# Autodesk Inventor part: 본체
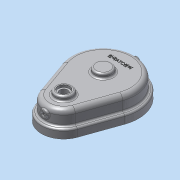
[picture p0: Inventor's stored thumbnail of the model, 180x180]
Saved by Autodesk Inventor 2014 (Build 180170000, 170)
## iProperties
Created: 2024-05
Part Number: 본체
Material: 알루미늄 6061
Document SubType Name: Modeling
Designer: dg
Density: 2.71 g/cm^3
Appearance: 알루미늄 - 평지
Mass: 509.144 g
Surface Area: 646.283 cm^2
Volume: 187.876 cm^3
Author: dg
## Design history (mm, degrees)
sketch "스케치1"
  geometry: L1 (-58.454, -20.667)-(-36.77, -82); L2 (58.454, -20.667)-(36.77, -82); A1 r 62 centre (0, 0) between (-58.454, -20.667) and (58.454, -20.667); A2 r 39 centre (0, -69) between (-36.77, -82) and (36.77, -82); 1 further point
  constraints: 4 end point, 4 point on circle, 4 tangent, 2 centre point, 1 coincident, 1 vertical alignment
  dimensions: "d0" = 124 diameter of A1; "d1" = 78 diameter of A2; "d2" = 69 distance of A2.centre point (0, 0)
extrude "돌출1" new body sketch "스케치1" distance "d3" = 15; taper "d4" = 0 deg
sketch "스케치2"
  geometry: L1 (52.797, -18.667)-(31.113, -80); L2 (-52.797, -18.667)-(-31.113, -80); A1 r 62 centre (0, 0) between (58.454, -20.667) and (-58.454, -20.667) reference; A2 r 39 centre (0, -69) between (-36.77, -82) and (36.77, -82) reference; A3 r 56 centre (0, 0) between (52.797, -18.667) and (-52.797, -18.667); A4 r 33 centre (0, -69) between (-31.113, -80) and (31.113, -80)
  constraints: 4 end point, 4 point on circle, 4 tangent, 2 centre point, 2 coincident
  dimensions: "d5" = 112 diameter of A3; "d6" = 66 diameter of A4
extrude "돌출2" join sketch "스케치2" distance "d7" = 25; taper "d8" = 0 deg
sketch "스케치3"
  geometry: C1 r 15 at (0, 0); A1 r 56 centre (0, 0) between (52.797, -18.667) and (-52.797, -18.667) reference
  constraints: 1 centre point, 1 coincident
  dimensions: "d9" = 30 diameter of C1
extrude "돌출3" join sketch "스케치3" distance "d10" = 8; taper "d11" = 0 deg
sketch "스케치4"
  geometry: C1 r 15 at (0, -69); A1 r 33 centre (0, -69) between (-31.113, -80) and (31.113, -80) reference
  constraints: 1 centre point, 1 coincident
  dimensions: "d12" = 30 diameter of C1
extrude "돌출4" join sketch "스케치4" distance "d13" = 8; taper "d14" = 0 deg
sketch "스케치5"
  geometry: L1 (48.083, -17)-(26.399, -78.333); L2 (-48.083, -17)-(-26.399, -78.333); A1 r 39 centre (0, -69) between (-36.77, -82) and (36.77, -82) reference; A2 r 62 centre (0, 0) between (58.454, -20.667) and (-58.454, -20.667) reference; A3 r 51 centre (0, 0) between (48.083, -17) and (-48.083, -17); A4 r 28 centre (0, -69) between (-26.399, -78.333) and (26.399, -78.333)
  constraints: 4 end point, 4 point on circle, 4 tangent, 2 centre point, 2 coincident
  dimensions: "d15" = 102 diameter of A3; "d16" = 56 diameter of A4
extrude "돌출5" cut sketch "스케치5" distance "d17" = 35; taper "d18" = 0 deg
sketch "스케치6"
  geometry: C1 r 14 at (0, 0); A1 r 51 centre (0, 0) between (48.083, -17) and (-48.083, -17) reference
  constraints: 1 centre point, 1 coincident
  dimensions: "d19" = 28 diameter of C1
extrude "돌출6" join sketch "스케치6" distance "d20" = 8; taper "d21" = 0 deg
sketch "스케치7"
  geometry: C1 r 14 at (0, -69); A1 r 28 centre (0, -69) between (-26.399, -78.333) and (26.399, -78.333) reference
  constraints: 1 centre point, 1 coincident
  dimensions: "d22" = 28 diameter of C1
extrude "돌출7" join sketch "스케치7" distance "d23" = 8; taper "d24" = 0 deg
hole "구멍1" diameter "d27" = 14; stored, may be unused: countersink angle "d31" = 90 deg, drill point angle "d33" = 0 deg; dims "d25" = 10, "d26" = 10, "d28" = 6, "d29" = 20, "d30" = 4.2, "d32" = 8
hole "구멍2" diameter "d36" = 14; stored, may be unused: countersink angle "d40" = 90 deg, drill point angle "d42" = 0 deg; dims "d34" = 10, "d35" = 10, "d37" = 6, "d38" = 20, "d39" = 4.2, "d41" = 10
sketch "스케치8"
  geometry: L1 (-18.667, 15)-(-18.667, 15) reference; L2 (-18.667, 15)-(-18.667, 40) reference; L3 (-18.667, 40)-(-18.667, 40) reference; L4 (-18.667, 15)-(-18.667, 40) reference; L5 (7, 27)-(-7, 27) reference; L6 (-7, 37)-(7, 37) reference; L7 (0, 39.309)-(4, 37); L8 (-4, 37)-(0, 39.309); L9 (0, 39.309)-(0, 37); 1 further point
  constraints: 6 end point, 2 point on line, 1 equal length, 1 midpoint, 1 perpendicular, 1 vertical alignment
  dimensions: "d45" = 8 distance of L7.end L8.start; "d46" = 120 deg angle of L8 L7
revolve "회전1" sketch "스케치8" stored, may be unused: angle "d47" = 90 deg
node "작업 평면1"
sketch "스케치9"
  geometry: L1 (56, 40)-(-56, 40) reference; L2 (62, 0)-(-62, 0) reference; C1 r 6 at (0, 28); 6 further points
  constraints: 1 centre point, 1 midpoint, 1 vertical alignment
  dimensions: "d49" = 12 diameter of C1; "d50" = 28 distance from line of L2 C1.centre
extrude "돌출8" join sketch "스케치9" stored distance "d51" = 8; taper "d52" = 0 deg
hole "구멍3" diameter "d55" = 5.188; stored, may be unused: countersink angle "d59" = 90 deg, drill point angle "d61" = 0 deg; dims "d56" = 100, "d57" = 7, "d58" = 2, "d60" = 10, "d64" = 10, "d65" = 10
node "작업 평면2"
sketch "스케치10"
  geometry: L1 (31.113, 40)-(-31.113, 40) reference; L2 (36.77, 0)-(-36.77, 0) reference; C1 r 6 at (0, 28); 2 further points
  constraints: 1 centre point, 1 midpoint, 1 vertical alignment
  dimensions: "d63" = 12 diameter of C1; "d66" = 28 distance from line of L2 C1.centre
extrude "돌출9" join sketch "스케치10" stored distance "d67" = 8; taper "d68" = 0 deg
hole "구멍4" diameter "d71" = 5.188; stored, may be unused: countersink angle "d75" = 90 deg, drill point angle "d77" = 0 deg; dims "d72" = 15, "d73" = 7, "d74" = 2, "d76" = 10, "d78" = 10, "d79" = 10
sketch "스케치11"
  geometry: L1 (52.797, -18.667)-(31.113, -80); L2 (-52.797, -18.667)-(-30.561, -81.56); L3 (0, 0)-(39.598, 39.598); L4 (0, 0)-(0, 56); L5 (0, 0)-(-39.598, 39.598); A1 r 28 centre (0, -69) between (-26.399, -78.333) and (26.399, -78.333) reference; A2 r 51 centre (0, 0) between (48.083, -17) and (-48.083, -17) reference; A3 r 39 centre (0, -69) between (-36.77, -82) and (36.77, -82) reference; A4 r 62 centre (0, 0) between (58.454, -20.667) and (-58.454, -20.667) reference; A5 r 56 centre (0, 0) between (52.797, -18.667) and (-52.797, -18.667); A6 r 33 centre (0, -69) between (-31.113, -80) and (31.113, -80); 8 further points
  constraints: 10 end point, 9 point on circle, 4 symmetric about line, 4 tangent, 3 point on line, 2 centre point, 2 horizontal alignment, 1 coincident, 1 concentric, 1 perpendicular, 1 vertical
  dimensions: "d80" = 112 diameter of A5; "d81" = 66 diameter of A6; "d82" = 34 vertical distance of point (56, 0) point (47.376, -34); "d83" = 45 deg angle of L4 L3; "d109" = 45 deg angle of L4 L5 (derived)
hole "구멍5" sketch "스케치11" at (56, 0), (35.002, -69), (47.376, -34), (0, -102), (0, 56), (-56, 0), (-47.376, -34), (-35.002, -69), (39.598, 39.598), (-39.598, 39.598) diameter "d84" = 3.242; stored, may be unused: countersink angle "d88" = 90 deg, drill point angle "d90" = 118 deg; dims "d85" = 8, "d86" = 7, "d87" = 2, "d89" = 10
fillet "모깎기1" dims "d91" = 3
fillet "모깎기2" dims "d92" = 3
fillet "모깎기3" dims "d93" = 8
fillet "모깎기4" dims "d94" = 3
fillet "모깎기5" dims "d95" = 3
fillet "모깎기6" dims "d96" = 3
fillet "모깎기7" dims "d97" = 3
fillet "모깎기8" dims "d98" = 3
chamfer "모따기1" distance "d99" = 1; stored, may be unused: second distance "d100" = 2, angle "d101" = 45 deg
sketch "스케치12"
  geometry: L1 (-79, 48)-(-59, 48) reference; L2 (-59, 43.8)-(-79, 43.8) reference; L3 (-54, 45)-(-84, 45) reference; L4 (-81, 48)-(-57, 48) reference; L5 (-79, 47.6)-(-79.231, 48); L6 (-79, 43.8)-(-79, 48) reference; L7 (-69, 48)-(-69, 42.459); L8 (-79.231, 48)-(-79, 48); L9 (-79, 47.6)-(-79, 48); 1 further point
  constraints: 8 end point, 2 collinear, 2 point on line, 1 midpoint, 1 perpendicular
  dimensions: "d102" = 0.4 distance from line of L4 L5.start; "d103" = 30 deg angle of L6 L5
revolve "회전2" sketch "스케치12" stored, may be unused: angle "d104" = 90 deg
sketch "스케치13"
  geometry: C1 r 18 at (0, 0) reference; 1 further point
  constraints: 1 vertical alignment, 1 other
  dimensions: "d105" = 30 distance of C1.centre point (0, 30)
feature "엠보싱1" sketch "스케치13" dims "d0" = 124, "d1" = 78, "d2" = 69, "d106" = 0.5, "d107" = 0
fillet "모깎기9" dims "d108" = 0.1
node "솔리드1"
node "투영된 루프1"
node "투영된 루프2"
node "투영된 루프3"
node "투영된 루프4"
other parameters: "d48" = 59, "d62" = -105
